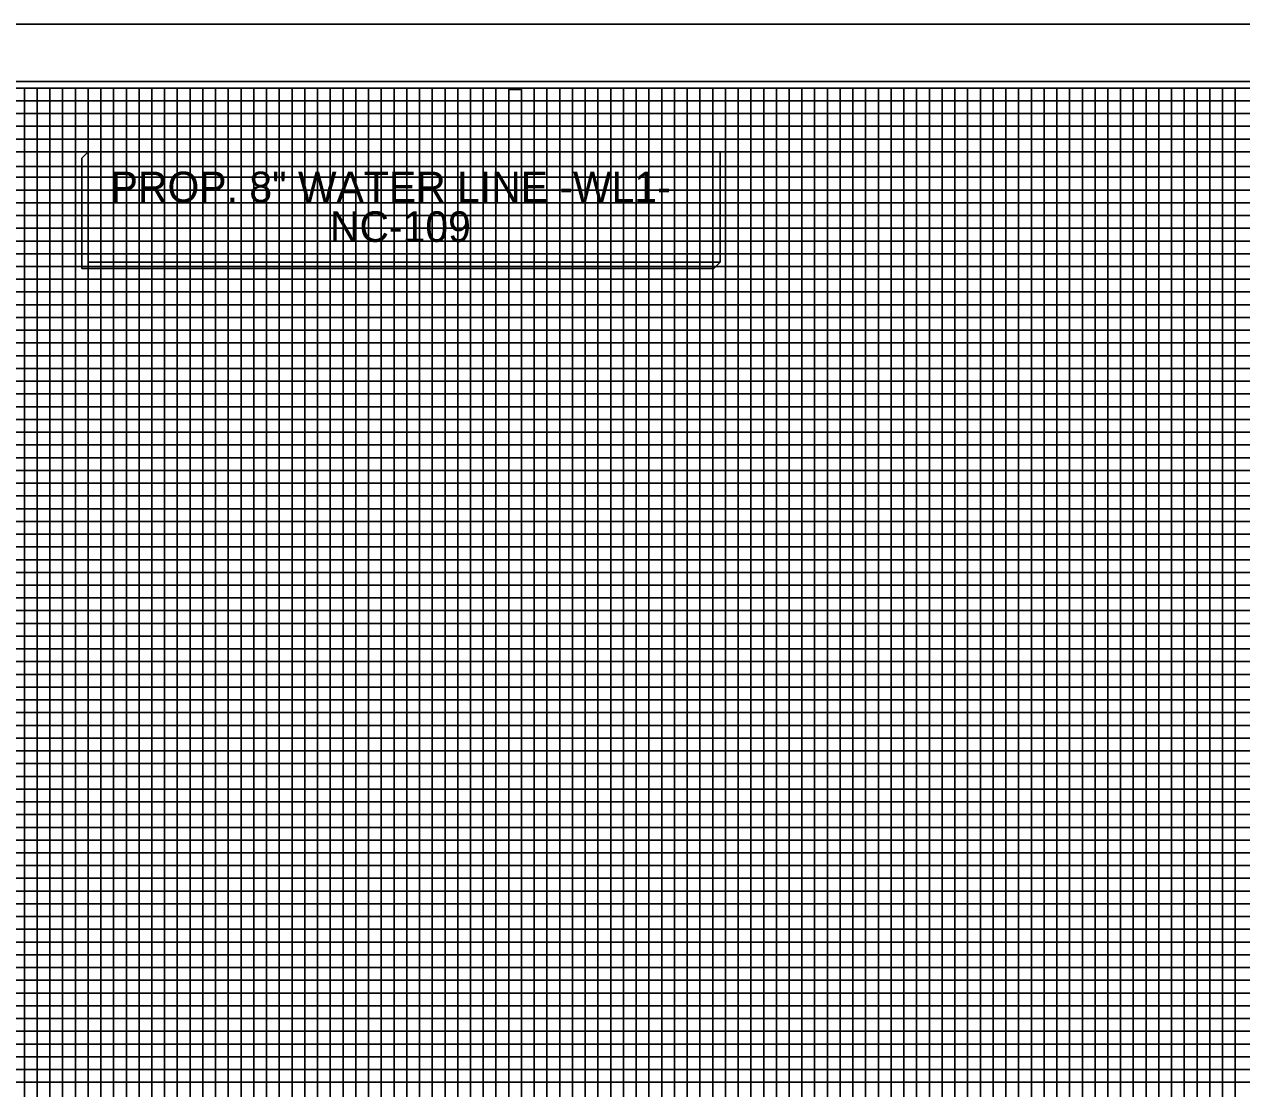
# Model space of a CAD drawing. Extents: x 1439200 to 3815465, y 598050 to 1224643.
# Drawn here: x 3815088.1 to 3815279.1, y 1224476.2 to 1224643.2 of the extents above; entities that cross this region are included whole.
import ezdxf

# ---------------------------------------------------------------- set-up
doc = ezdxf.new("R2010")
doc.units = 0
for name, color, linetype in [('COGO Default Chain', 7, 'Continuous'), ('Exist Roads EOP', 7, 'Continuous'), ('Pattern 49', 7, 'Continuous'), ('Scratch_Level_1', 7, 'Continuous')]:
    doc.layers.add(name, color=color, linetype=linetype)

msp = doc.modelspace()

# ---------------------------------------------------------------- linework, layer by layer
at = {"layer": 'COGO Default Chain'}
for p, q in [((3815097.11, 1224622.19), (3815098.11, 1224623.19)), ((3815197.29, 1224605.91), (3815196.29, 1224604.91)), ((3815197.29, 1224605.91), (3815196.29, 1224604.91))]:
    msp.add_line(p, q, dxfattribs=at)
for points in [[(3815196.29, 1224604.91), (3815097.11, 1224604.91), (3815097.11, 1224622.19)], [(3815098.11, 1224623.19), (3815098.11, 1224605.91), (3815197.29, 1224605.91)]]:
    msp.add_lwpolyline(points, dxfattribs=at)
msp.add_lwpolyline([(3815098.11, 1224623.19), (3815197.29, 1224623.19), (3815197.29, 1224605.91), (3815098.11, 1224605.91)], close=True, dxfattribs=at)
at = {"layer": 'Exist Roads EOP'}
for p, q in [((3814878.11, 1224633.21), (3815378.11, 1224633.21)), ((3815438.11, 1224561.21), (3814878.11, 1224561.21)), ((3814878.11, 1224559.21), (3815438.11, 1224559.21)), ((3815438.11, 1224551.21), (3814878.11, 1224551.21))]:
    msp.add_line(p, q, dxfattribs=at)
for points in [[(3815458.11, 1224633.21), (3814858.11, 1224633.21), (3814858.11, 1224213.21), (3815458.11, 1224213.21)], [(3814878.11, 1224633.21), (3814878.11, 1224223.21), (3815438.11, 1224223.21), (3815438.11, 1224578.19), (3815378.11, 1224578.19), (3815378.11, 1224633.21)]]:
    msp.add_lwpolyline(points, close=True, dxfattribs=at)
for points in [[(3815088.11, 1224223.21), (3815088.11, 1224633.21), (3815108.11, 1224633.21), (3815108.11, 1224223.21)], [(3815090.11, 1224223.21), (3815090.11, 1224633.21), (3815092.11, 1224633.21), (3815092.11, 1224223.21)], [(3815094.11, 1224223.21), (3815094.11, 1224633.21), (3815096.11, 1224633.21), (3815096.11, 1224223.21)], [(3815098.11, 1224223.21), (3815098.11, 1224633.21), (3815118.11, 1224633.21), (3815118.11, 1224223.21)], [(3815100.11, 1224223.21), (3815100.11, 1224633.21), (3815102.11, 1224633.21), (3815102.11, 1224223.21)], [(3815104.11, 1224223.21), (3815104.11, 1224633.21), (3815106.11, 1224633.21), (3815106.11, 1224223.21)], [(3815110.11, 1224223.21), (3815110.11, 1224633.21), (3815112.11, 1224633.21), (3815112.11, 1224223.21)], [(3815114.11, 1224223.21), (3815114.11, 1224633.21), (3815116.11, 1224633.21), (3815116.11, 1224223.21)], [(3815120.11, 1224223.21), (3815120.11, 1224633.21), (3815122.11, 1224633.21), (3815122.11, 1224223.21)], [(3815124.11, 1224223.21), (3815124.11, 1224633.21), (3815126.11, 1224633.21), (3815126.11, 1224223.21)], [(3815128.11, 1224223.21), (3815128.11, 1224633.21), (3815148.11, 1224633.21), (3815148.11, 1224223.21)], [(3815130.11, 1224223.21), (3815130.11, 1224633.21), (3815132.11, 1224633.21), (3815132.11, 1224223.21)], [(3815134.11, 1224223.21), (3815134.11, 1224633.21), (3815136.11, 1224633.21), (3815136.11, 1224223.21)], [(3815138.11, 1224223.21), (3815138.11, 1224633.21), (3815158.11, 1224633.21), (3815158.11, 1224223.21)], [(3815140.11, 1224223.21), (3815140.11, 1224633.21), (3815142.11, 1224633.21), (3815142.11, 1224223.21)], [(3815144.11, 1224223.21), (3815144.11, 1224633.21), (3815146.11, 1224633.21), (3815146.11, 1224223.21)], [(3815150.11, 1224223.21), (3815150.11, 1224633.21), (3815152.11, 1224633.21), (3815152.11, 1224223.21)], [(3815154.11, 1224223.21), (3815154.11, 1224633.21), (3815156.11, 1224633.21), (3815156.11, 1224223.21)], [(3815160.11, 1224223.21), (3815160.11, 1224633.21), (3815162.11, 1224633.21), (3815162.11, 1224223.21)], [(3815164.11, 1224223.21), (3815164.11, 1224632.97), (3815166.11, 1224632.97), (3815166.11, 1224223.21)], [(3815168.11, 1224223.21), (3815168.11, 1224633.21), (3815188.11, 1224633.21), (3815188.11, 1224223.21)], [(3815170.11, 1224223.21), (3815170.11, 1224633.21), (3815172.11, 1224633.21), (3815172.11, 1224223.21)], [(3815174.11, 1224223.21), (3815174.11, 1224633.21), (3815176.11, 1224633.21), (3815176.11, 1224223.21)], [(3815178.11, 1224223.21), (3815178.11, 1224633.21), (3815198.11, 1224633.21), (3815198.11, 1224223.21)], [(3815180.11, 1224223.21), (3815180.11, 1224633.21), (3815182.11, 1224633.21), (3815182.11, 1224223.21)], [(3815184.11, 1224223.21), (3815184.11, 1224633.21), (3815186.11, 1224633.21), (3815186.11, 1224223.21)], [(3815190.11, 1224223.21), (3815190.11, 1224633.21), (3815192.11, 1224633.21), (3815192.11, 1224223.21)], [(3815194.11, 1224223.21), (3815194.11, 1224633.21), (3815196.11, 1224633.21), (3815196.11, 1224223.21)], [(3815200.11, 1224223.21), (3815200.11, 1224633.21), (3815202.11, 1224633.21), (3815202.11, 1224223.21)], [(3815204.11, 1224223.21), (3815204.11, 1224633.21), (3815206.11, 1224633.21), (3815206.11, 1224223.21)], [(3815208.11, 1224223.21), (3815208.11, 1224633.21), (3815228.11, 1224633.21), (3815228.11, 1224223.21)], [(3815210.11, 1224223.21), (3815210.11, 1224633.21), (3815212.11, 1224633.21), (3815212.11, 1224223.21)], [(3815214.11, 1224223.21), (3815214.11, 1224633.21), (3815216.11, 1224633.21), (3815216.11, 1224223.21)], [(3815218.11, 1224223.21), (3815218.11, 1224633.21), (3815238.11, 1224633.21), (3815238.11, 1224223.21)], [(3815220.11, 1224223.21), (3815220.11, 1224633.21), (3815222.11, 1224633.21), (3815222.11, 1224223.21)], [(3815224.11, 1224223.21), (3815224.11, 1224633.21), (3815226.11, 1224633.21), (3815226.11, 1224223.21)], [(3815230.11, 1224223.21), (3815230.11, 1224633.21), (3815232.11, 1224633.21), (3815232.11, 1224223.21)], [(3815234.11, 1224223.21), (3815234.11, 1224633.21), (3815236.11, 1224633.21), (3815236.11, 1224223.21)], [(3815240.11, 1224223.21), (3815240.11, 1224633.21), (3815242.11, 1224633.21), (3815242.11, 1224223.21)], [(3815244.11, 1224223.21), (3815244.11, 1224633.21), (3815246.11, 1224633.21), (3815246.11, 1224223.21)], [(3815248.11, 1224223.21), (3815248.11, 1224633.21), (3815268.11, 1224633.21), (3815268.11, 1224223.21)], [(3815250.11, 1224223.21), (3815250.11, 1224633.21), (3815252.11, 1224633.21), (3815252.11, 1224223.21)], [(3815254.11, 1224223.21), (3815254.11, 1224633.21), (3815256.11, 1224633.21), (3815256.11, 1224223.21)], [(3815258.11, 1224223.21), (3815258.11, 1224633.21), (3815278.11, 1224633.21), (3815278.11, 1224223.21)], [(3815260.11, 1224223.21), (3815260.11, 1224633.21), (3815262.11, 1224633.21), (3815262.11, 1224223.21)], [(3815264.11, 1224223.21), (3815264.11, 1224633.21), (3815266.11, 1224633.21), (3815266.11, 1224223.21)], [(3815270.11, 1224223.21), (3815270.11, 1224633.21), (3815272.11, 1224633.21), (3815272.11, 1224223.21)], [(3815274.11, 1224223.21), (3815274.11, 1224633.21), (3815276.11, 1224633.21), (3815276.11, 1224223.21)], [(3815378.09, 1224631.21), (3814878.11, 1224631.21), (3814878.11, 1224629.21), (3815378.09, 1224629.21)], [(3815378.09, 1224627.21), (3814878.11, 1224627.21), (3814878.11, 1224625.21), (3815378.09, 1224625.21)], [(3815378.09, 1224603.21), (3814858.15, 1224603.21), (3814858.15, 1224623.19), (3815378.09, 1224623.19)], [(3815378.09, 1224620.91), (3814878.11, 1224620.91), (3814878.11, 1224619.21), (3815378.09, 1224619.21)], [(3815378.09, 1224617.21), (3814878.11, 1224617.21), (3814878.11, 1224615.21), (3815378.09, 1224615.21)], [(3814858.11, 1224613.21), (3815378.09, 1224613.21)], [(3815378.09, 1224611.21), (3814878.11, 1224611.21), (3814878.11, 1224609.21), (3815378.09, 1224609.21)], [(3815378.11, 1224607.21), (3814878.11, 1224607.21), (3814878.11, 1224605.21), (3815378.09, 1224605.21)], [(3815378.09, 1224601.21), (3814878.11, 1224601.21), (3814878.11, 1224599.21), (3815378.09, 1224599.21)], [(3815378.09, 1224597.21), (3814878.11, 1224597.21), (3814878.11, 1224595.21), (3815378.09, 1224595.21)], [(3815378.09, 1224593.21), (3814858.11, 1224593.21), (3814858.11, 1224573.19), (3815458.11, 1224573.19)], [(3815378.09, 1224591.21), (3814878.11, 1224591.21), (3814878.11, 1224589.21), (3815378.09, 1224589.21)], [(3815378.09, 1224587.21), (3814878.11, 1224587.21), (3814878.11, 1224585.21), (3815378.09, 1224585.21)], [(3815458.11, 1224563.21), (3814858.11, 1224563.21), (3814858.11, 1224583.21), (3815378.09, 1224583.21)], [(3815378.09, 1224581.21), (3814878.11, 1224581.21), (3814878.11, 1224579.21), (3815378.09, 1224579.21)], [(3815438.11, 1224577.21), (3814878.11, 1224577.21), (3814878.11, 1224577.21), (3814878.11, 1224569.21), (3815438.11, 1224569.21)], [(3815438.11, 1224577.21), (3814878.11, 1224577.21), (3814878.11, 1224577.21), (3814878.11, 1224569.21), (3815458.11, 1224569.21)], [(3814878.11, 1224575.21), (3815438.11, 1224575.21)], [(3815438.11, 1224571.21), (3814878.11, 1224571.21)], [(3815438.11, 1224567.21), (3814878.11, 1224567.21), (3814878.11, 1224565.21), (3815438.11, 1224565.21)], [(3815438.11, 1224557.21), (3814878.11, 1224557.21), (3814878.11, 1224555.21), (3815438.11, 1224555.21)], [(3815458.11, 1224553.21), (3814858.11, 1224553.21), (3814858.11, 1224533.21), (3815458.11, 1224533.21)], [(3815438.11, 1224549.21), (3814878.11, 1224549.21), (3814878.11, 1224547.21), (3815438.11, 1224547.21)], [(3815438.11, 1224545.21), (3814878.11, 1224545.21)], [(3815458.11, 1224523.21), (3814858.11, 1224523.21), (3814858.11, 1224543.21), (3815458.11, 1224543.21)], [(3814878.11, 1224541.21), (3815438.11, 1224541.21)], [(3815438.11, 1224539.21), (3814878.11, 1224539.21), (3814878.11, 1224537.21), (3815438.11, 1224537.21)], [(3815438.11, 1224535.21), (3814878.11, 1224535.21), (3814878.11, 1224531.21), (3815438.11, 1224531.21)], [(3815438.11, 1224529.21), (3814878.11, 1224529.21), (3814878.11, 1224527.21), (3815438.11, 1224527.21)], [(3815438.11, 1224525.21), (3814878.11, 1224525.21), (3814878.11, 1224521.21), (3815438.11, 1224521.21)], [(3815438.11, 1224519.21), (3814878.11, 1224519.21), (3814878.11, 1224517.21), (3815438.11, 1224517.21)], [(3815438.11, 1224515.21), (3814878.11, 1224515.21), (3814878.11, 1224511.21), (3815438.11, 1224511.21)], [(3815458.11, 1224513.21), (3814858.11, 1224513.21), (3814858.11, 1224493.21), (3815458.11, 1224493.21)], [(3815438.11, 1224509.21), (3814878.11, 1224509.21), (3814878.11, 1224507.21), (3815438.11, 1224507.21)], [(3815438.11, 1224505.21), (3814878.11, 1224505.21), (3814878.11, 1224501.21), (3815438.11, 1224501.21)], [(3815458.11, 1224483.21), (3814858.11, 1224483.21), (3814858.11, 1224503.21), (3815458.11, 1224503.21)], [(3815438.11, 1224499.21), (3814878.11, 1224499.21), (3814878.11, 1224497.21), (3815438.11, 1224497.21)], [(3815438.11, 1224495.21), (3814878.11, 1224495.21), (3814878.11, 1224491.21), (3815438.11, 1224491.21)], [(3815438.11, 1224489.21), (3814878.11, 1224489.21), (3814878.11, 1224487.21), (3815438.11, 1224487.21)], [(3815438.11, 1224485.21), (3814878.11, 1224485.21), (3814878.11, 1224481.21), (3815438.11, 1224481.21)], [(3815438.11, 1224479.21), (3814878.11, 1224479.21), (3814878.11, 1224477.21), (3815438.11, 1224477.21)]]:
    msp.add_lwpolyline(points, dxfattribs=at)
at = {"layer": 'Pattern 49'}
msp.add_lwpolyline([(3815463.11, 1224634.23), (3814796.51, 1224634.23), (3814796.51, 1224212.19), (3815463.11, 1224212.19)], close=True, dxfattribs=at)
at = {"layer": 'Scratch_Level_1'}
msp.add_lwpolyline([(3815464.91, 1224643.21), (3814791.31, 1224643.21), (3814791.31, 1224203.21), (3815464.91, 1224203.21)], close=True, dxfattribs=at)

# ---------------------------------------------------------------- texts
at = {"layer": 'COGO Default Chain'}
for s, p in [('PROP. 8" WATER LINE -WL1-', (3815101.65, 1224615.29)), ('NC-109', (3815136.05, 1224609.07))]:
    msp.add_text(s, height=4.8, rotation=360, dxfattribs=at).set_placement(p)

doc.saveas('drawing.dxf')
